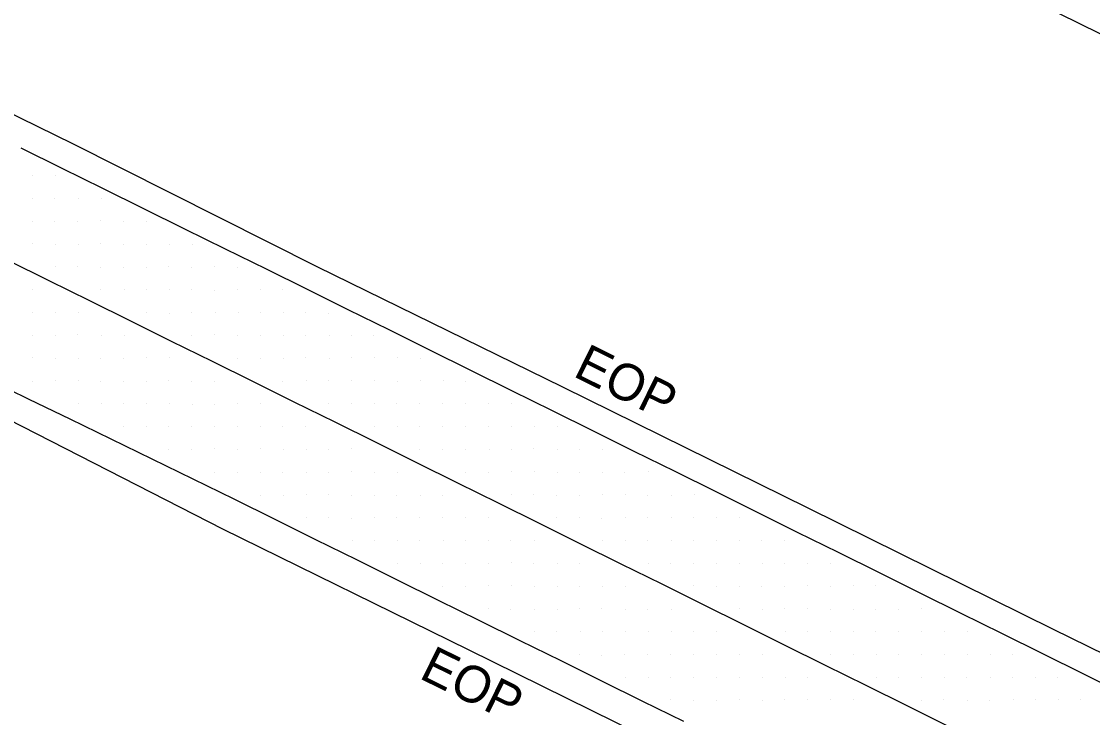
# Model space of a CAD drawing. Extents: x 2244337 to 2251208, y 199469 to 202984.
# Drawn here: x 2244517.9 to 2244635.3, y 202725.8 to 202802.1 of the extents above; entities that cross this region are included whole.
import ezdxf

# ---------------------------------------------------------------- set-up
doc = ezdxf.new("R2010")
doc.units = 0
for name, color, linetype in [('Exist DTM Scan Elevation Point', 7, 'Continuous'), ('Exist Roads EOP', 7, 'Continuous'), ('Exist Roads EOT', 7, 'Continuous'), ('Exist Roads Text', 7, 'Continuous')]:
    doc.layers.add(name, color=color, linetype=linetype)

msp = doc.modelspace()

# ---------------------------------------------------------------- linework, layer by layer
at = {"layer": 'Exist DTM Scan Elevation Point'}
for p, q in [((2244519.12, 202785.24), (2244519.12, 202785.24)), ((2244521.56, 202785.23), (2244521.56, 202785.23)), ((2244519.07, 202782.72), (2244519.07, 202782.72)), ((2244521.55, 202782.71), (2244521.55, 202782.71)), ((2244524.12, 202782.72), (2244524.12, 202782.72)), ((2244526.61, 202782.71), (2244526.61, 202782.71)), ((2244519.1, 202780.18), (2244519.1, 202780.18)), ((2244521.53, 202780.23), (2244521.53, 202780.23)), ((2244524.06, 202780.19), (2244524.06, 202780.19)), ((2244526.59, 202780.27), (2244526.59, 202780.27)), ((2244529.1, 202780.25), (2244529.1, 202780.25)), ((2244531.57, 202780.19), (2244531.57, 202780.19)), ((2244519.09, 202777.73), (2244519.09, 202777.73)), ((2244521.58, 202777.71), (2244521.58, 202777.71)), ((2244524.08, 202777.71), (2244524.08, 202777.71)), ((2244526.56, 202777.77), (2244526.56, 202777.77)), ((2244529.06, 202777.68), (2244529.06, 202777.68)), ((2244531.6, 202777.69), (2244531.6, 202777.69)), ((2244534.1, 202777.71), (2244534.1, 202777.71)), ((2244536.58, 202777.7), (2244536.58, 202777.7)), ((2244521.57, 202775.23), (2244521.57, 202775.23)), ((2244524.06, 202775.24), (2244524.06, 202775.24)), ((2244526.55, 202775.19), (2244526.55, 202775.19)), ((2244529.09, 202775.2), (2244529.09, 202775.2)), ((2244531.6, 202775.2), (2244531.6, 202775.2)), ((2244534.03, 202775.22), (2244534.03, 202775.22)), ((2244536.57, 202775.2), (2244536.57, 202775.2)), ((2244539.07, 202775.24), (2244539.07, 202775.24)), ((2244541.57, 202775.19), (2244541.57, 202775.19)), ((2244519.1, 202772.69), (2244519.1, 202772.69)), ((2244526.57, 202772.7), (2244526.57, 202772.7)), ((2244529.14, 202772.73), (2244529.14, 202772.73)), ((2244531.63, 202772.73), (2244531.63, 202772.73)), ((2244534.09, 202772.73), (2244534.09, 202772.73)), ((2244536.56, 202772.69), (2244536.56, 202772.69)), ((2244539.07, 202772.68), (2244539.07, 202772.68)), ((2244541.61, 202772.7), (2244541.61, 202772.7)), ((2244544.04, 202772.7), (2244544.04, 202772.7)), ((2244546.51, 202772.73), (2244546.51, 202772.73)), ((2244519.1, 202770.22), (2244519.1, 202770.22)), ((2244521.56, 202770.21), (2244521.56, 202770.21)), ((2244524.09, 202770.2), (2244524.09, 202770.2)), ((2244531.6, 202770.21), (2244531.6, 202770.21)), ((2244534.08, 202770.16), (2244534.08, 202770.16)), ((2244536.51, 202770.23), (2244536.51, 202770.23)), ((2244539.1, 202770.18), (2244539.1, 202770.18)), ((2244541.63, 202770.2), (2244541.63, 202770.2)), ((2244544.08, 202770.23), (2244544.08, 202770.23)), ((2244546.56, 202770.22), (2244546.56, 202770.22)), ((2244549.07, 202770.25), (2244549.07, 202770.25)), ((2244551.57, 202770.15), (2244551.57, 202770.15)), ((2244524.04, 202767.78), (2244524.04, 202767.78)), ((2244519.12, 202767.68), (2244519.12, 202767.68)), ((2244521.6, 202767.73), (2244521.6, 202767.73)), ((2244526.64, 202767.68), (2244526.64, 202767.68)), ((2244529.13, 202767.7), (2244529.13, 202767.7)), ((2244536.57, 202767.74), (2244536.57, 202767.74)), ((2244539.04, 202767.75), (2244539.04, 202767.75)), ((2244541.54, 202767.72), (2244541.54, 202767.72)), ((2244544.11, 202767.73), (2244544.11, 202767.73)), ((2244546.59, 202767.73), (2244546.59, 202767.73)), ((2244549.07, 202767.66), (2244549.07, 202767.66)), ((2244551.61, 202767.71), (2244551.61, 202767.71)), ((2244554.11, 202767.71), (2244554.11, 202767.71)), ((2244556.52, 202767.69), (2244556.52, 202767.69)), ((2244519.07, 202765.26), (2244519.07, 202765.26)), ((2244521.57, 202765.22), (2244521.57, 202765.22)), ((2244524.08, 202765.18), (2244524.08, 202765.18)), ((2244526.57, 202765.17), (2244526.57, 202765.17)), ((2244529.05, 202765.18), (2244529.05, 202765.18)), ((2244531.56, 202765.24), (2244531.56, 202765.24)), ((2244534.12, 202765.25), (2244534.12, 202765.25)), ((2244541.62, 202765.22), (2244541.62, 202765.22)), ((2244544.06, 202765.19), (2244544.06, 202765.19)), ((2244546.59, 202765.16), (2244546.59, 202765.16)), ((2244549.03, 202765.24), (2244549.03, 202765.24)), ((2244551.61, 202765.19), (2244551.61, 202765.19)), ((2244554.09, 202765.24), (2244554.09, 202765.24)), ((2244556.6, 202765.26), (2244556.6, 202765.26)), ((2244559.07, 202765.24), (2244559.07, 202765.24)), ((2244561.58, 202765.21), (2244561.58, 202765.21)), ((2244519.06, 202762.67), (2244519.06, 202762.67)), ((2244521.57, 202762.73), (2244521.57, 202762.73)), ((2244524.09, 202762.75), (2244524.09, 202762.75)), ((2244526.56, 202762.7), (2244526.56, 202762.7)), ((2244529.07, 202762.7), (2244529.07, 202762.7)), ((2244531.57, 202762.7), (2244531.57, 202762.7)), ((2244534.02, 202762.72), (2244534.02, 202762.72)), ((2244536.55, 202762.7), (2244536.55, 202762.7)), ((2244539.08, 202762.7), (2244539.08, 202762.7)), ((2244546.54, 202762.69), (2244546.54, 202762.69)), ((2244549.12, 202762.74), (2244549.12, 202762.74)), ((2244551.55, 202762.73), (2244551.55, 202762.73)), ((2244554.05, 202762.71), (2244554.05, 202762.71)), ((2244556.6, 202762.73), (2244556.6, 202762.73)), ((2244559.07, 202762.7), (2244559.07, 202762.7)), ((2244561.6, 202762.73), (2244561.6, 202762.73)), ((2244564.12, 202762.73), (2244564.12, 202762.73)), ((2244566.58, 202762.7), (2244566.58, 202762.7)), ((2244524.12, 202760.23), (2244524.12, 202760.23)), ((2244526.64, 202760.22), (2244526.64, 202760.22)), ((2244529.03, 202760.22), (2244529.03, 202760.22)), ((2244531.57, 202760.2), (2244531.57, 202760.2)), ((2244534.12, 202760.2), (2244534.12, 202760.2)), ((2244536.6, 202760.18), (2244536.6, 202760.18)), ((2244539.08, 202760.18), (2244539.08, 202760.18)), ((2244541.54, 202760.22), (2244541.54, 202760.22)), ((2244544.09, 202760.21), (2244544.09, 202760.21)), ((2244551.59, 202760.19), (2244551.59, 202760.19)), ((2244554.09, 202760.2), (2244554.09, 202760.2)), ((2244556.58, 202760.2), (2244556.58, 202760.2)), ((2244559.02, 202760.24), (2244559.02, 202760.24)), ((2244561.54, 202760.21), (2244561.54, 202760.21)), ((2244564.03, 202760.21), (2244564.03, 202760.21)), ((2244566.58, 202760.25), (2244566.58, 202760.25)), ((2244569.1, 202760.23), (2244569.1, 202760.23)), ((2244571.59, 202760.21), (2244571.59, 202760.21)), ((2244529.05, 202757.67), (2244529.05, 202757.67)), ((2244531.61, 202757.67), (2244531.61, 202757.67)), ((2244534.05, 202757.73), (2244534.05, 202757.73)), ((2244536.57, 202757.72), (2244536.57, 202757.72)), ((2244539.08, 202757.72), (2244539.08, 202757.72)), ((2244541.62, 202757.74), (2244541.62, 202757.74)), ((2244544.05, 202757.7), (2244544.05, 202757.7)), ((2244546.52, 202757.71), (2244546.52, 202757.71)), ((2244549.04, 202757.67), (2244549.04, 202757.67)), ((2244556.6, 202757.68), (2244556.6, 202757.68)), ((2244559.07, 202757.74), (2244559.07, 202757.74)), ((2244561.52, 202757.73), (2244561.52, 202757.73)), ((2244564.07, 202757.7), (2244564.07, 202757.7)), ((2244566.56, 202757.73), (2244566.56, 202757.73)), ((2244569.12, 202757.7), (2244569.12, 202757.7)), ((2244571.56, 202757.68), (2244571.56, 202757.68)), ((2244574.1, 202757.72), (2244574.1, 202757.72)), ((2244576.62, 202757.7), (2244576.62, 202757.7)), ((2244534.02, 202755.21), (2244534.02, 202755.21)), ((2244536.57, 202755.21), (2244536.57, 202755.21)), ((2244539.08, 202755.25), (2244539.08, 202755.25)), ((2244541.56, 202755.17), (2244541.56, 202755.17)), ((2244544.11, 202755.25), (2244544.11, 202755.25)), ((2244546.59, 202755.22), (2244546.59, 202755.22)), ((2244549.11, 202755.19), (2244549.11, 202755.19)), ((2244551.57, 202755.24), (2244551.57, 202755.24)), ((2244554.05, 202755.27), (2244554.05, 202755.27)), ((2244561.57, 202755.24), (2244561.57, 202755.24)), ((2244564.08, 202755.18), (2244564.08, 202755.18)), ((2244566.54, 202755.24), (2244566.54, 202755.24)), ((2244569.15, 202755.18), (2244569.15, 202755.18)), ((2244571.59, 202755.21), (2244571.59, 202755.21)), ((2244574.05, 202755.25), (2244574.05, 202755.25)), ((2244576.63, 202755.21), (2244576.63, 202755.21)), ((2244579.05, 202755.19), (2244579.05, 202755.19)), ((2244581.59, 202755.21), (2244581.59, 202755.21)), ((2244539.07, 202752.72), (2244539.07, 202752.72)), ((2244541.55, 202752.71), (2244541.55, 202752.71)), ((2244544.05, 202752.72), (2244544.05, 202752.72)), ((2244546.54, 202752.7), (2244546.54, 202752.7)), ((2244549.12, 202752.72), (2244549.12, 202752.72)), ((2244551.58, 202752.72), (2244551.58, 202752.72)), ((2244554.11, 202752.75), (2244554.11, 202752.75)), ((2244556.61, 202752.7), (2244556.61, 202752.7)), ((2244559.08, 202752.69), (2244559.08, 202752.69)), ((2244566.62, 202752.72), (2244566.62, 202752.72)), ((2244569.07, 202752.72), (2244569.07, 202752.72)), ((2244571.58, 202752.73), (2244571.58, 202752.73)), ((2244574.1, 202752.74), (2244574.1, 202752.74)), ((2244576.6, 202752.7), (2244576.6, 202752.7)), ((2244579.1, 202752.71), (2244579.1, 202752.71)), ((2244581.57, 202752.67), (2244581.57, 202752.67)), ((2244584.03, 202752.69), (2244584.03, 202752.69)), ((2244586.58, 202752.73), (2244586.58, 202752.73)), ((2244544.09, 202750.2), (2244544.09, 202750.2)), ((2244546.58, 202750.18), (2244546.58, 202750.18)), ((2244549.08, 202750.21), (2244549.08, 202750.21)), ((2244551.57, 202750.24), (2244551.57, 202750.24)), ((2244554.07, 202750.19), (2244554.07, 202750.19)), ((2244556.56, 202750.17), (2244556.56, 202750.17)), ((2244559.05, 202750.16), (2244559.05, 202750.16)), ((2244561.59, 202750.2), (2244561.59, 202750.2)), ((2244564.07, 202750.18), (2244564.07, 202750.18)), ((2244571.56, 202750.23), (2244571.56, 202750.23)), ((2244574.07, 202750.21), (2244574.07, 202750.21)), ((2244576.58, 202750.18), (2244576.58, 202750.18)), ((2244579.03, 202750.19), (2244579.03, 202750.19)), ((2244581.62, 202750.21), (2244581.62, 202750.21)), ((2244584.08, 202750.24), (2244584.08, 202750.24)), ((2244586.55, 202750.2), (2244586.55, 202750.2)), ((2244589.1, 202750.19), (2244589.1, 202750.19)), ((2244591.63, 202750.22), (2244591.63, 202750.22)), ((2244549.08, 202747.69), (2244549.08, 202747.69)), ((2244551.54, 202747.76), (2244551.54, 202747.76)), ((2244554.11, 202747.68), (2244554.11, 202747.68)), ((2244556.6, 202747.71), (2244556.6, 202747.71)), ((2244559.05, 202747.71), (2244559.05, 202747.71)), ((2244561.56, 202747.71), (2244561.56, 202747.71)), ((2244564.09, 202747.74), (2244564.09, 202747.74)), ((2244566.55, 202747.74), (2244566.55, 202747.74)), ((2244569.09, 202747.73), (2244569.09, 202747.73)), ((2244576.58, 202747.71), (2244576.58, 202747.71)), ((2244579.07, 202747.71), (2244579.07, 202747.71)), ((2244581.53, 202747.68), (2244581.53, 202747.68)), ((2244584.11, 202747.73), (2244584.11, 202747.73)), ((2244586.57, 202747.71), (2244586.57, 202747.71)), ((2244589.1, 202747.71), (2244589.1, 202747.71)), ((2244591.59, 202747.7), (2244591.59, 202747.7)), ((2244594.11, 202747.73), (2244594.11, 202747.73)), ((2244596.58, 202747.74), (2244596.58, 202747.74)), ((2244554.13, 202745.21), (2244554.13, 202745.21)), ((2244556.57, 202745.18), (2244556.57, 202745.18)), ((2244559.07, 202745.23), (2244559.07, 202745.23)), ((2244561.57, 202745.22), (2244561.57, 202745.22)), ((2244564.1, 202745.23), (2244564.1, 202745.23)), ((2244566.56, 202745.18), (2244566.56, 202745.18)), ((2244569.06, 202745.19), (2244569.06, 202745.19)), ((2244571.54, 202745.23), (2244571.54, 202745.23)), ((2244574.12, 202745.22), (2244574.12, 202745.22)), ((2244581.6, 202745.2), (2244581.6, 202745.2)), ((2244584.14, 202745.19), (2244584.14, 202745.19)), ((2244586.56, 202745.2), (2244586.56, 202745.2)), ((2244589.15, 202745.21), (2244589.15, 202745.21)), ((2244591.6, 202745.2), (2244591.6, 202745.2)), ((2244594.1, 202745.19), (2244594.1, 202745.19)), ((2244596.56, 202745.26), (2244596.56, 202745.26)), ((2244599.06, 202745.26), (2244599.06, 202745.26)), ((2244601.59, 202745.26), (2244601.59, 202745.26)), ((2244559.09, 202742.67), (2244559.09, 202742.67)), ((2244561.59, 202742.73), (2244561.59, 202742.73)), ((2244564.06, 202742.72), (2244564.06, 202742.72)), ((2244566.58, 202742.71), (2244566.58, 202742.71)), ((2244569.07, 202742.73), (2244569.07, 202742.73)), ((2244571.56, 202742.76), (2244571.56, 202742.76)), ((2244574.07, 202742.69), (2244574.07, 202742.69)), ((2244576.6, 202742.71), (2244576.6, 202742.71)), ((2244579.08, 202742.7), (2244579.08, 202742.7)), ((2244586.58, 202742.72), (2244586.58, 202742.72)), ((2244589.07, 202742.69), (2244589.07, 202742.69)), ((2244591.55, 202742.69), (2244591.55, 202742.69)), ((2244594.08, 202742.69), (2244594.08, 202742.69)), ((2244596.58, 202742.71), (2244596.58, 202742.71)), ((2244599.11, 202742.71), (2244599.11, 202742.71)), ((2244601.58, 202742.69), (2244601.58, 202742.69)), ((2244604.09, 202742.7), (2244604.09, 202742.7)), ((2244606.61, 202742.68), (2244606.61, 202742.68)), ((2244564.03, 202740.2), (2244564.03, 202740.2)), ((2244566.58, 202740.2), (2244566.58, 202740.2)), ((2244569.05, 202740.25), (2244569.05, 202740.25)), ((2244571.58, 202740.23), (2244571.58, 202740.23)), ((2244574.1, 202740.2), (2244574.1, 202740.2)), ((2244576.6, 202740.22), (2244576.6, 202740.22)), ((2244579.07, 202740.2), (2244579.07, 202740.2)), ((2244581.6, 202740.19), (2244581.6, 202740.19)), ((2244584.06, 202740.22), (2244584.06, 202740.22)), ((2244591.61, 202740.23), (2244591.61, 202740.23)), ((2244594.08, 202740.22), (2244594.08, 202740.22)), ((2244596.58, 202740.18), (2244596.58, 202740.18)), ((2244599.07, 202740.2), (2244599.07, 202740.2)), ((2244601.59, 202740.21), (2244601.59, 202740.21)), ((2244604.05, 202740.23), (2244604.05, 202740.23)), ((2244606.59, 202740.22), (2244606.59, 202740.22)), ((2244609.11, 202740.25), (2244609.11, 202740.25)), ((2244611.55, 202740.25), (2244611.55, 202740.25)), ((2244569.04, 202737.74), (2244569.04, 202737.74)), ((2244571.52, 202737.69), (2244571.52, 202737.69)), ((2244574.09, 202737.64), (2244574.09, 202737.64)), ((2244576.6, 202737.68), (2244576.6, 202737.68)), ((2244579.1, 202737.73), (2244579.1, 202737.73)), ((2244581.53, 202737.72), (2244581.53, 202737.72)), ((2244584.07, 202737.68), (2244584.07, 202737.68)), ((2244586.54, 202737.7), (2244586.54, 202737.7)), ((2244589.13, 202737.68), (2244589.13, 202737.68)), ((2244596.56, 202737.71), (2244596.56, 202737.71)), ((2244599.11, 202737.7), (2244599.11, 202737.7)), ((2244601.54, 202737.72), (2244601.54, 202737.72)), ((2244604.1, 202737.74), (2244604.1, 202737.74)), ((2244606.59, 202737.69), (2244606.59, 202737.69)), ((2244609.1, 202737.68), (2244609.1, 202737.68)), ((2244611.56, 202737.67), (2244611.56, 202737.67)), ((2244614.05, 202737.69), (2244614.05, 202737.69)), ((2244616.56, 202737.73), (2244616.56, 202737.73)), ((2244574.1, 202735.21), (2244574.1, 202735.21)), ((2244576.56, 202735.2), (2244576.56, 202735.2)), ((2244579.13, 202735.26), (2244579.13, 202735.26)), ((2244581.56, 202735.24), (2244581.56, 202735.24)), ((2244584.06, 202735.21), (2244584.06, 202735.21)), ((2244586.61, 202735.23), (2244586.61, 202735.23)), ((2244589.1, 202735.2), (2244589.1, 202735.2)), ((2244591.55, 202735.19), (2244591.55, 202735.19)), ((2244594.07, 202735.2), (2244594.07, 202735.2)), ((2244601.62, 202735.25), (2244601.62, 202735.25)), ((2244604.12, 202735.2), (2244604.12, 202735.2)), ((2244606.59, 202735.19), (2244606.59, 202735.19)), ((2244609.06, 202735.24), (2244609.06, 202735.24)), ((2244611.57, 202735.2), (2244611.57, 202735.2)), ((2244614.09, 202735.23), (2244614.09, 202735.23)), ((2244616.54, 202735.22), (2244616.54, 202735.22)), ((2244619.12, 202735.21), (2244619.12, 202735.21)), ((2244621.58, 202735.21), (2244621.58, 202735.21)), ((2244579.1, 202732.71), (2244579.1, 202732.71)), ((2244581.53, 202732.65), (2244581.53, 202732.65)), ((2244584.05, 202732.69), (2244584.05, 202732.69)), ((2244586.57, 202732.7), (2244586.57, 202732.7)), ((2244589.07, 202732.73), (2244589.07, 202732.73)), ((2244591.56, 202732.74), (2244591.56, 202732.74)), ((2244594.12, 202732.72), (2244594.12, 202732.72)), ((2244596.58, 202732.71), (2244596.58, 202732.71)), ((2244599.08, 202732.72), (2244599.08, 202732.72)), ((2244606.56, 202732.69), (2244606.56, 202732.69)), ((2244609.07, 202732.72), (2244609.07, 202732.72)), ((2244611.65, 202732.73), (2244611.65, 202732.73)), ((2244614.07, 202732.68), (2244614.07, 202732.68)), ((2244616.61, 202732.75), (2244616.61, 202732.75)), ((2244619.09, 202732.72), (2244619.09, 202732.72)), ((2244621.58, 202732.76), (2244621.58, 202732.76)), ((2244624.08, 202732.71), (2244624.08, 202732.71)), ((2244626.58, 202732.7), (2244626.58, 202732.7)), ((2244584.11, 202730.22), (2244584.11, 202730.22)), ((2244586.6, 202730.22), (2244586.6, 202730.22)), ((2244589.07, 202730.18), (2244589.07, 202730.18)), ((2244591.57, 202730.24), (2244591.57, 202730.24)), ((2244594.1, 202730.21), (2244594.1, 202730.21)), ((2244596.58, 202730.2), (2244596.58, 202730.2)), ((2244599.1, 202730.23), (2244599.1, 202730.23)), ((2244601.61, 202730.24), (2244601.61, 202730.24)), ((2244604.08, 202730.24), (2244604.08, 202730.24)), ((2244611.59, 202730.21), (2244611.59, 202730.21)), ((2244614.08, 202730.2), (2244614.08, 202730.2)), ((2244616.59, 202730.24), (2244616.59, 202730.24)), ((2244619.05, 202730.18), (2244619.05, 202730.18)), ((2244621.55, 202730.22), (2244621.55, 202730.22)), ((2244624.12, 202730.24), (2244624.12, 202730.24)), ((2244626.58, 202730.18), (2244626.58, 202730.18)), ((2244629.06, 202730.21), (2244629.06, 202730.21)), ((2244631.53, 202730.21), (2244631.53, 202730.21)), ((2244589.06, 202727.73), (2244589.06, 202727.73)), ((2244591.57, 202727.71), (2244591.57, 202727.71)), ((2244594.09, 202727.71), (2244594.09, 202727.71)), ((2244596.57, 202727.73), (2244596.57, 202727.73)), ((2244599.09, 202727.68), (2244599.09, 202727.68)), ((2244601.55, 202727.73), (2244601.55, 202727.73)), ((2244604.09, 202727.73), (2244604.09, 202727.73)), ((2244606.54, 202727.75), (2244606.54, 202727.75)), ((2244609.1, 202727.74), (2244609.1, 202727.74)), ((2244616.54, 202727.71), (2244616.54, 202727.71)), ((2244619.03, 202727.73), (2244619.03, 202727.73)), ((2244621.57, 202727.67), (2244621.57, 202727.67)), ((2244624.04, 202727.72), (2244624.04, 202727.72)), ((2244626.63, 202727.76), (2244626.63, 202727.76)), ((2244629.07, 202727.73), (2244629.07, 202727.73)), ((2244631.59, 202727.74), (2244631.59, 202727.74)), ((2244634.05, 202727.73), (2244634.05, 202727.73))]:
    msp.add_line(p, q, dxfattribs=at)
at = {"layer": 'Exist Roads EOP'}
for points in [[(2244958.85, 202641.19), (2244931.98, 202654.52), (2244905.1, 202667.85), (2244878.24, 202681.21), (2244851.36, 202694.53), (2244824.43, 202707.74), (2244797.54, 202721.05), (2244770.65, 202734.35), (2244743.76, 202747.66), (2244716.89, 202760.99), (2244690.18, 202774.66), (2244663.01, 202787.42), (2244636.15, 202800.76), (2244609.26, 202814.04), (2244582.35, 202827.29), (2244555.46, 202840.63), (2244528.66, 202854.11), (2244501.78, 202867.44), (2244474.81, 202880.57), (2244448.01, 202894.05), (2244421.03, 202907.17), (2244394.33, 202920.84), (2244380.98, 202927.4)], [(2244351.85, 202873.14), (2244361.93, 202868.19), (2244388.91, 202855.07), (2244415.86, 202841.9), (2244442.67, 202828.42), (2244469.58, 202815.17), (2244496.52, 202801.95), (2244523.46, 202788.76), (2244550.26, 202775.27), (2244577.19, 202762.06), (2244604.11, 202748.8), (2244630.99, 202735.49), (2244657.92, 202722.28), (2244684.9, 202709.17), (2244711.73, 202695.73), (2244738.6, 202682.38), (2244765.5, 202669.1), (2244792.27, 202655.56), (2244819.23, 202642.39), (2244846.1, 202629.06), (2244872.91, 202615.58), (2244899.9, 202602.49), (2244926.63, 202588.88), (2244953.56, 202575.64)], [(2244943.48, 202547.28), (2244916.63, 202560.66), (2244889.68, 202573.83), (2244862.84, 202587.23), (2244835.88, 202600.4), (2244809.11, 202613.95), (2244782.35, 202627.51), (2244755.34, 202640.56), (2244728.54, 202654.04), (2244701.77, 202667.58), (2244674.67, 202680.46), (2244647.54, 202693.28), (2244620.76, 202706.79), (2244593.8, 202719.97), (2244566.9, 202733.24), (2244539.97, 202746.47), (2244513.27, 202760.09), (2244486.33, 202773.29), (2244459.38, 202786.53), (2244432.4, 202799.65), (2244405.41, 202812.75), (2244378.55, 202826.13), (2244351.63, 202839.37), (2244337.48, 202846.37)]]:
    msp.add_lwpolyline(points, dxfattribs=at)
at = {"layer": 'Exist Roads EOT'}
for points in [[(2244517.81, 202788.27), (2244522.29, 202786.05), (2244526.77, 202783.84), (2244531.26, 202781.63), (2244535.74, 202779.41), (2244540.22, 202777.2), (2244544.71, 202774.99), (2244549.19, 202772.78), (2244553.67, 202770.56), (2244558.15, 202768.34), (2244562.63, 202766.12), (2244567.12, 202763.9), (2244571.6, 202761.68), (2244576.08, 202759.47), (2244580.56, 202757.24), (2244585.04, 202755.02), (2244589.52, 202752.8), (2244594, 202750.58), (2244598.48, 202748.36), (2244602.95, 202746.14), (2244607.43, 202743.92), (2244611.91, 202741.7), (2244616.39, 202739.48), (2244620.87, 202737.26), (2244625.35, 202735.04), (2244629.83, 202732.82), (2244634.32, 202730.6), (2244638.8, 202728.38)], [(2244516.39, 202775.95), (2244520.87, 202773.74), (2244525.35, 202771.52), (2244529.83, 202769.3), (2244534.31, 202767.09), (2244538.8, 202764.87), (2244543.28, 202762.65), (2244547.76, 202760.43), (2244552.24, 202758.21), (2244556.72, 202755.99), (2244561.2, 202753.77), (2244565.68, 202751.55), (2244570.16, 202749.33), (2244574.64, 202747.11), (2244579.12, 202744.89), (2244583.6, 202742.67), (2244588.08, 202740.45), (2244592.56, 202738.23), (2244597.04, 202736), (2244601.52, 202733.78), (2244605.99, 202731.56), (2244610.47, 202729.34), (2244614.95, 202727.12), (2244619.43, 202724.9)], [(2244590.49, 202725.35), (2244586.01, 202727.56), (2244581.53, 202729.78), (2244577.05, 202732), (2244572.57, 202734.22), (2244568.08, 202736.43), (2244563.6, 202738.65), (2244559.12, 202740.87), (2244554.64, 202743.08), (2244550.16, 202745.3), (2244545.68, 202747.52), (2244541.19, 202749.73), (2244536.71, 202751.95), (2244532.22, 202754.14), (2244527.72, 202756.33), (2244523.22, 202758.51), (2244518.72, 202760.69), (2244514.22, 202762.87)]]:
    msp.add_lwpolyline(points, dxfattribs=at)

# ---------------------------------------------------------------- texts
at = {"layer": 'Exist Roads Text'}
for rotation, p in [(333.7798, (2244578.24, 202763.28)), (333.7482, (2244561.36, 202730.17))]:
    msp.add_text('EOP', height=4.02, rotation=rotation, dxfattribs=at).set_placement(p)

doc.saveas('drawing.dxf')
